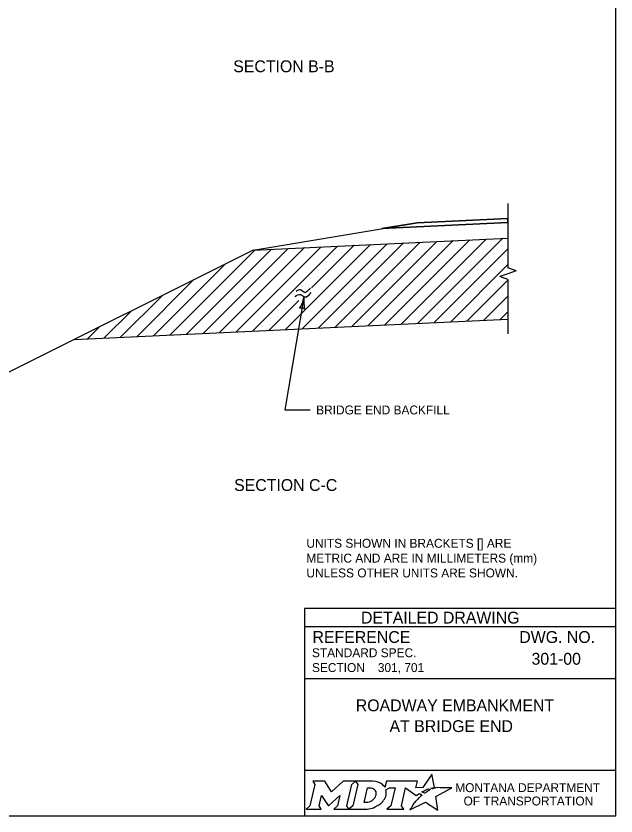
# Model space of a CAD drawing. Extents: x 49991.4 to 50021, y 49987.6 to 50011.4.
# Drawn here: x 50004.57 to 50008.61, y 50000.06 to 50005.46 of the extents above; entities that cross this region are included whole.
import ezdxf

# ---------------------------------------------------------------- set-up
doc = ezdxf.new("R2010")
doc.units = 0
for name, color, linetype in [('Level 1', 7, 'Continuous'), ('Level 2', 7, 'Continuous'), ('Level 3', 7, 'Continuous'), ('Level 6', 7, 'Continuous')]:
    doc.layers.add(name, color=color, linetype=linetype)

msp = doc.modelspace()

# ---------------------------------------------------------------- linework, layer by layer
at = {"layer": 'Level 1'}
for p, q in [((50006.1678, 50003.878), (50007.2752, 50004.0625)), ((50007.886, 50004.0628), (50007.0367, 50004.0228)), ((50007.2752, 50004.0625), (50007.886, 50004.0913)), ((50006.1678, 50003.878), (50007.886, 50003.959)), ((50006.9438, 50003.3684), (50007.517, 50003.9416)), ((50007.0551, 50003.3737), (50007.6283, 50003.9468)), ((50007.1664, 50003.3789), (50007.7396, 50003.9521)), ((50007.2777, 50003.3842), (50007.8509, 50003.9573)), ((50005.8306, 50003.3159), (50006.4038, 50003.8891)), ((50005.9419, 50003.3212), (50006.5151, 50003.8943)), ((50006.0533, 50003.3264), (50006.6264, 50003.8996)), ((50006.1646, 50003.3317), (50006.7378, 50003.9048)), ((50006.3872, 50003.3422), (50006.9604, 50003.9153)), ((50006.4985, 50003.3474), (50007.0717, 50003.9206)), ((50006.5618, 50003.6228), (50006.8491, 50003.9101)), ((50006.6098, 50003.3527), (50007.183, 50003.9258)), ((50006.7212, 50003.3579), (50007.2943, 50003.9311)), ((50006.8325, 50003.3632), (50007.4057, 50003.9363)), ((50007.3891, 50003.3894), (50007.886, 50003.8864)), ((50006.1678, 50003.878), (50003.9187, 50002.7534)), ((50005.608, 50003.3054), (50006.1812, 50003.8786)), ((50005.7193, 50003.3107), (50006.2925, 50003.8838)), ((50005.4967, 50003.3001), (50005.9812, 50003.7847)), ((50007.5004, 50003.3947), (50007.886, 50003.7803)), ((50005.3854, 50003.2949), (50005.7691, 50003.6786)), ((50007.6117, 50003.3999), (50007.886, 50003.6742)), ((50005.274, 50003.2896), (50005.5569, 50003.5725)), ((50007.723, 50003.4052), (50007.886, 50003.5682)), ((50006.2759, 50003.3369), (50006.477, 50003.538)), ((50005.1627, 50003.2844), (50005.3448, 50003.4665)), ((50007.8343, 50003.4104), (50007.886, 50003.4621)), ((50005.0514, 50003.2791), (50005.1327, 50003.3604))]:
    msp.add_line(p, q, dxfattribs=at)
msp.add_lwpolyline([(50008.6146, 50011.2628), (50000.3356, 50011.2628), (50000.3356, 50000.0624), (50008.6146, 50000.0624)], close=True, dxfattribs=at)
for points in [[(50007.886, 50004.0628), (50007.886, 50004.0913), (50007.2752, 50004.0625), (50007.0367, 50004.0228), (50007.886, 50004.0628)], [(50004.9617, 50003.2749), (50007.886, 50003.4129)]]:
    msp.add_lwpolyline(points, dxfattribs=at)
at = {"layer": 'Level 2'}
for p, q in [((50008.6146, 50001.4624), (50006.5146, 50001.4624)), ((50006.5146, 50001.4624), (50006.5146, 50000.0624)), ((50008.6146, 50001.3374), (50006.5146, 50001.3374)), ((50008.2507, 50001.1223), (50008.2507, 50001.1223)), ((50007.0089, 50001.0629), (50007.0089, 50001.0629)), ((50008.6146, 50000.9874), (50006.5146, 50000.9874)), ((50007.5646, 50000.7383), (50007.5646, 50000.7383)), ((50008.6146, 50000.3693), (50006.5146, 50000.3693))]:
    msp.add_line(p, q, dxfattribs=at)
for points in [[(50007.3771, 50000.2447), (50007.3668, 50000.2503), (50007.3784, 50000.2531), (50007.39, 50000.2551), (50007.3726, 50000.3452), (50007.3131, 50000.2539), (50007.2658, 50000.2532), (50007.2761, 50000.2973), (50007.0669, 50000.2974), (50007.0568, 50000.2549), (50007.051, 50000.2632)], [(50006.5701, 50000.2974), (50006.5842, 50000.274), (50006.5507, 50000.1307), (50006.525, 50000.1082), (50006.6266, 50000.1082), (50006.6131, 50000.131), (50006.6293, 50000.2011), (50006.673, 50000.1321), (50006.6783, 50000.1321), (50006.7534, 50000.2016), (50006.737, 50000.1305), (50006.7123, 50000.1085), (50006.8139, 50000.1085), (50006.8001, 50000.1318), (50006.8333, 50000.2742)], [(50006.8333, 50000.2742), (50006.8586, 50000.2974), (50006.7762, 50000.2974), (50006.6966, 50000.2244), (50006.6521, 50000.2971), (50006.5701, 50000.2974)], [(50006.9722, 50000.2974), (50006.8586, 50000.2974), (50006.8733, 50000.2745), (50006.8394, 50000.1307), (50006.8139, 50000.1085), (50006.9245, 50000.1085)], [(50006.9962, 50000.2107), (50006.995, 50000.2026), (50006.9918, 50000.1933), (50006.9876, 50000.1851), (50006.982, 50000.1776), (50006.9755, 50000.1707), (50006.9676, 50000.1644), (50006.9593, 50000.1597), (50006.9502, 50000.1558), (50006.9411, 50000.1535), (50006.9319, 50000.1526), (50006.916, 50000.1526), (50006.9396, 50000.2526), (50006.9556, 50000.2526), (50006.9632, 50000.252), (50006.9708, 50000.2501), (50006.9774, 50000.2471), (50006.9835, 50000.2429), (50006.9883, 50000.2379), (50006.992, 50000.2319), (50006.9947, 50000.2257), (50006.9963, 50000.2183), (50006.9963, 50000.2153), (50006.9962, 50000.2107)], [(50007.0636, 50000.2383), (50007.0882, 50000.2514), (50007.1251, 50000.2514), (50007.0965, 50000.1309), (50007.069, 50000.1082), (50007.1852, 50000.1082), (50007.1682, 50000.1311), (50007.1964, 50000.2513), (50007.2677, 50000.1996), (50007.2888, 50000.2147), (50007.3085, 50000.2038)], [(50007.2527, 50000.1479), (50007.2374, 50000.1235), (50007.2327, 50000.116), (50007.2269, 50000.1074), (50007.2246, 50000.1031), (50007.3299, 50000.1562), (50007.4138, 50000.1011), (50007.4007, 50000.1938), (50007.5076, 50000.2522), (50007.4583, 50000.253), (50007.4282, 50000.2534), (50007.4074, 50000.2537), (50007.4006, 50000.2522), (50007.3957, 50000.251), (50007.3873, 50000.2487), (50007.3771, 50000.2447)], [(50007.3267, 50000.2171), (50007.3243, 50000.2154), (50007.306, 50000.225), (50007.3163, 50000.2307), (50007.3204, 50000.2329), (50007.329, 50000.2369), (50007.3347, 50000.2395), (50007.3426, 50000.2425), (50007.3499, 50000.2452), (50007.3617, 50000.2378), (50007.3577, 50000.2357), (50007.3531, 50000.2332), (50007.3489, 50000.231), (50007.3439, 50000.2281), (50007.342, 50000.227), (50007.3393, 50000.2254), (50007.3368, 50000.224), (50007.3345, 50000.2224), (50007.3319, 50000.2206), (50007.3292, 50000.2188), (50007.3267, 50000.2171)], [(50007.2666, 50000.164), (50007.2666, 50000.164)], [(50006.9702, 50000.1158), (50006.9786, 50000.1184), (50006.9916, 50000.1238), (50007.012, 50000.1348)]]:
    msp.add_lwpolyline(points, dxfattribs=at)
for centre, radius, start, end in [((50006.9953, 50000.219), 0.0709, 339.5329, 15.8582), ((50006.9513, 50000.2363), 0.1183, 300.9103, 339.1383)]:
    msp.add_arc(centre, radius, start, end, dxfattribs=at)
for centre, major_axis, ratio, start_param, end_param in [((50006.9701, 50000.25), (0.0834, -0.0037), 0.568097, 0.61298, 1.570796), ((50007.0257, 50000.2573), (0.0361, -0.0295), 0.469099, 1.225588, 1.570796), ((50007.2597, 50000.1559), (-0.00694, -0.00806), 0.008222, 0, 3.137361), ((50007.2764, 50000.1742), (-0.0098, -0.0102), 0.016458, 3.141593, 6.279097), ((50007.2974, 50000.1941), (-0.0112, -0.0097), 0.021651, 3.157348, 6.283185), ((50006.9248, 50000.2568), (0, 0.1484), 0.987302, 3.139398, 3.456847)]:
    msp.add_ellipse(centre, major_axis=major_axis, ratio=ratio, start_param=start_param, end_param=end_param, dxfattribs=at)
at = {"layer": 'Level 3'}
for p, q in [((50006.5108, 50003.558), (50006.383, 50002.7998)), ((50006.383, 50002.7998), (50006.5531, 50002.7998))]:
    msp.add_line(p, q, dxfattribs=at)
for centre, radius, start, end in [((50006.2933, 50003.6039), 0.2223, 327.8884, 348.0719), ((50006.7422, 50003.5306), 0.233, 173.2597, 192.5095), ((50006.4895, 50003.4315), 0.0548, 62.5712, 98.2935)]:
    msp.add_arc(centre, radius, start, end, dxfattribs=at)
at = {"layer": 'Level 6'}
for p, q in [((50007.886, 50004.1913), (50007.886, 50003.8412)), ((50007.886, 50003.8412), (50007.886, 50003.7576)), ((50007.9408, 50003.7381), (50007.886, 50003.7576)), ((50007.9408, 50003.7381), (50007.886, 50003.7187)), ((50007.886, 50003.7187), (50007.8312, 50003.6993)), ((50007.886, 50003.6798), (50007.8312, 50003.6993)), ((50007.886, 50003.6798), (50007.886, 50003.3129))]:
    msp.add_line(p, q, dxfattribs=at)
for points in [[(50006.4583, 50003.6009), (50006.4868, 50003.6117), (50006.5179, 50003.5928), (50006.5395, 50003.6076), (50006.5558, 50003.6224)], [(50006.4502, 50003.5645), (50006.4881, 50003.5779), (50006.5165, 50003.5618), (50006.5585, 50003.5914)]]:
    msp.add_spline(points, degree=3, dxfattribs=at)

# ---------------------------------------------------------------- texts
at = {"layer": 'Level 2'}
for s, height, p in [('SECTION B-B', 0.08, (50006.034, 50005.077)), ('BRIDGE END BACKFILL', 0.06, (50006.5931, 50002.7698)), ('SECTION C-C', 0.08, (50006.0399, 50002.2538)), ('UNITS SHOWN IN BRACKETS [] ARE ', 0.06, (50006.5272, 50001.871)), ('METRIC AND ARE IN MILLIMETERS (mm) ', 0.06, (50006.5272, 50001.771)), ('UNLESS OTHER UNITS ARE SHOWN.', 0.06, (50006.5272, 50001.671)), ('DETAILED DRAWING', 0.0799, (50006.8956, 50001.3599)), ('REFERENCE', 0.08, (50006.5682, 50001.229)), ('DWG. NO.', 0.08, (50007.9624, 50001.229)), ('STANDARD SPEC.', 0.06, (50006.5649, 50001.133)), ('301-00', 0.08, (50008.0451, 50001.0823)), ('SECTION', 0.06, (50006.5649, 50001.033)), ('301, 701', 0.06, (50007.0089, 50001.0329)), ('ROADWAY EMBANKMENT', 0.08, (50006.8602, 50000.7683)), ('AT BRIDGE END', 0.08, (50007.0876, 50000.6283)), ('MONTANA DEPARTMENT', 0.06, (50007.5308, 50000.2236)), ('OF TRANSPORTATION', 0.06, (50007.587, 50000.1336))]:
    msp.add_text(s, height=height, dxfattribs=at).set_placement(p)

doc.saveas('drawing.dxf')
